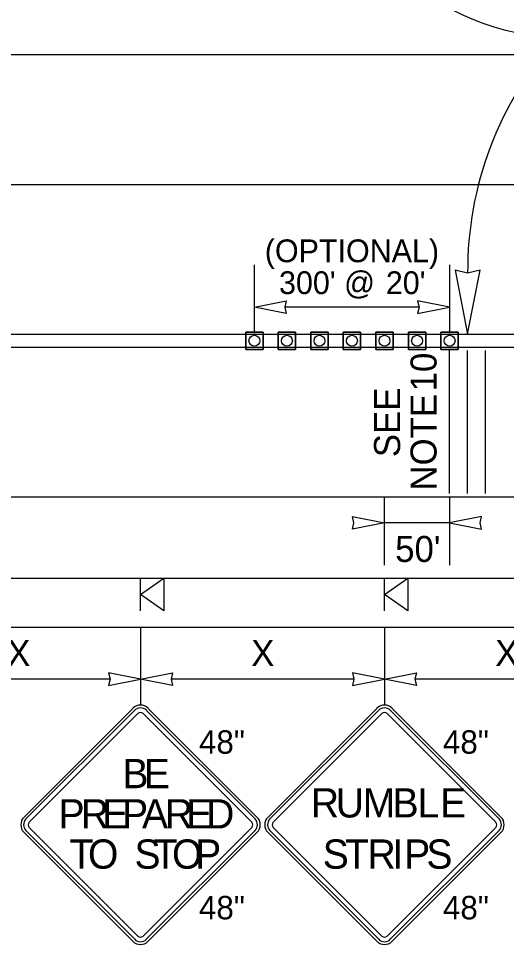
# Model space of a CAD drawing. Extents: x 99999.1 to 100095.7, y 99995 to 100010.7.
# Drawn here: x 100001.652 to 100003.152, y 100004.757 to 100007.603 of the extents above; entities that cross this region are included whole.
import ezdxf

# ---------------------------------------------------------------- set-up
doc = ezdxf.new("R2010")
doc.units = 0
for name, color, linetype in [('RD_ED_ShoulderPavedEdge', 7, 'Continuous'), ('RD_MK_LineDblYellowCenter', 7, 'Continuous'), ('RD_MK_LineEdgeWhite', 7, 'Continuous'), ('TR_SN_ConstructionSigns', 7, 'Continuous'), ('TR_WZ_PortableSignMountBlk-Org', 7, 'Continuous'), ('TR_WZ_TrafficCone', 7, 'Continuous'), ('TR_WZ_WorkZoneDetails', 7, 'Continuous'), ('TR_WZ_WorkZoneTextCurrent', 7, 'Continuous')]:
    doc.layers.add(name, color=color, linetype=linetype)

msp = doc.modelspace()

# ---------------------------------------------------------------- linework, layer by layer
at = {"layer": 'RD_ED_ShoulderPavedEdge'}
for p, q in [((100000.1076, 100007.4923), (100015.6424, 100007.4923)), ((100000.1076, 100005.7323), (100015.6424, 100005.7323))]:
    msp.add_line(p, q, dxfattribs=at)
at = {"layer": 'RD_MK_LineDblYellowCenter'}
for p, q in [((100000.1282, 100006.6323), (100003.4767, 100006.6323)), ((100000.0869, 100006.5923), (100003.4767, 100006.5923))]:
    msp.add_line(p, q, dxfattribs=at)
at = {"layer": 'RD_MK_LineEdgeWhite'}
for p, q in [((100000.1076, 100007.0923), (100015.6424, 100007.0923)), ((100000.1076, 100006.1323), (100015.6424, 100006.1323))]:
    msp.add_line(p, q, dxfattribs=at)
at = {"layer": 'TR_SN_ConstructionSigns'}
for p, q in [((100002.0028, 100005.4824), (100001.6687, 100005.1483)), ((100002.0088, 100005.4765), (100001.6746, 100005.1424)), ((100002.3787, 100005.1424), (100002.0445, 100005.4765)), ((100002.3846, 100005.1483), (100002.0505, 100005.4824)), ((100002.7528, 100005.4824), (100002.4187, 100005.1483)), ((100002.7588, 100005.4765), (100002.4246, 100005.1424)), ((100003.1287, 100005.1424), (100002.7945, 100005.4765)), ((100003.1346, 100005.1483), (100002.8005, 100005.4824)), ((100001.6846, 100005.1324), (100002.0187, 100005.4665)), ((100002.0346, 100005.4665), (100002.3687, 100005.1324)), ((100002.4346, 100005.1324), (100002.7687, 100005.4665)), ((100002.7846, 100005.4665), (100003.1187, 100005.1324)), ((100001.6746, 100005.1066), (100002.0088, 100004.7725)), ((100002.0187, 100004.7824), (100001.6846, 100005.1165)), ((100002.3687, 100005.1165), (100002.0346, 100004.7824)), ((100002.0445, 100004.7725), (100002.3787, 100005.1066)), ((100002.4246, 100005.1066), (100002.7588, 100004.7725)), ((100002.7687, 100004.7824), (100002.4346, 100005.1165)), ((100003.1187, 100005.1165), (100002.7846, 100004.7824)), ((100002.7945, 100004.7725), (100003.1287, 100005.1066)), ((100001.6687, 100005.1006), (100002.0028, 100004.7665)), ((100002.0505, 100004.7665), (100002.3846, 100005.1006)), ((100002.4187, 100005.1006), (100002.7528, 100004.7665)), ((100002.8005, 100004.7665), (100003.1346, 100005.1006))]:
    msp.add_line(p, q, dxfattribs=at)
for centre, radius, start, end in [((100002.0267, 100005.4586), 0.0338, 45, 135), ((100002.0267, 100005.4586), 0.0253, 45, 135), ((100002.7767, 100005.4586), 0.0338, 45, 135), ((100002.7767, 100005.4586), 0.0253, 45, 135), ((100002.0267, 100005.4586), 0.0113, 45, 135), ((100002.7767, 100005.4586), 0.0113, 45, 135), ((100001.6925, 100005.1245), 0.0338, 135, 225), ((100001.6925, 100005.1245), 0.0253, 135, 225), ((100001.6925, 100005.1245), 0.0113, 135, 225), ((100002.3608, 100005.1245), 0.0113, 315, 45), ((100002.3608, 100005.1245), 0.0253, 315, 45), ((100002.3608, 100005.1245), 0.0338, 315, 45), ((100002.4425, 100005.1245), 0.0338, 135, 225), ((100002.4425, 100005.1245), 0.0253, 135, 225), ((100002.4425, 100005.1245), 0.0113, 135, 225), ((100003.1108, 100005.1245), 0.0113, 315, 45), ((100003.1108, 100005.1245), 0.0253, 315, 45), ((100003.1108, 100005.1245), 0.0338, 315, 45), ((100002.0267, 100004.7904), 0.0338, 225, 315), ((100002.0267, 100004.7904), 0.0253, 225, 315), ((100002.0267, 100004.7904), 0.0113, 225, 315), ((100002.7767, 100004.7904), 0.0338, 225, 315), ((100002.7767, 100004.7904), 0.0253, 225, 315), ((100002.7767, 100004.7904), 0.0113, 225, 315)]:
    msp.add_arc(centre, radius, start, end, dxfattribs=at)
at = {"layer": 'TR_WZ_PortableSignMountBlk-Org'}
for p, q in [((100002.0267, 100005.7824), (100002.0267, 100005.8824)), ((100002.7767, 100005.7824), (100002.7767, 100005.8824))]:
    msp.add_line(p, q, dxfattribs=at)
for points in [[(100002.0267, 100005.8323), (100002.0985, 100005.8824), (100002.0985, 100005.7824)], [(100002.7767, 100005.8323), (100002.8485, 100005.8824), (100002.8485, 100005.7824)]]:
    msp.add_lwpolyline(points, close=True, dxfattribs=at)
at = {"layer": 'TR_WZ_TrafficCone'}
for points in [[(100002.4033, 100006.639), (100002.35, 100006.639), (100002.35, 100006.5857), (100002.4033, 100006.5857), (100002.4033, 100006.639)], [(100002.4033, 100006.5857), (100002.35, 100006.5857), (100002.35, 100006.639), (100002.4033, 100006.639), (100002.4033, 100006.5857)], [(100002.5033, 100006.639), (100002.45, 100006.639), (100002.45, 100006.5857), (100002.5033, 100006.5857), (100002.5033, 100006.639)], [(100002.5033, 100006.5857), (100002.45, 100006.5857), (100002.45, 100006.639), (100002.5033, 100006.639), (100002.5033, 100006.5857)], [(100002.6033, 100006.639), (100002.55, 100006.639), (100002.55, 100006.5857), (100002.6033, 100006.5857), (100002.6033, 100006.639)], [(100002.6033, 100006.5857), (100002.55, 100006.5857), (100002.55, 100006.639), (100002.6033, 100006.639), (100002.6033, 100006.5857)], [(100002.7033, 100006.639), (100002.65, 100006.639), (100002.65, 100006.5857), (100002.7033, 100006.5857), (100002.7033, 100006.639)], [(100002.7033, 100006.5857), (100002.65, 100006.5857), (100002.65, 100006.639), (100002.7033, 100006.639), (100002.7033, 100006.5857)], [(100002.8033, 100006.639), (100002.75, 100006.639), (100002.75, 100006.5857), (100002.8033, 100006.5857), (100002.8033, 100006.639)], [(100002.8033, 100006.5857), (100002.75, 100006.5857), (100002.75, 100006.639), (100002.8033, 100006.639), (100002.8033, 100006.5857)], [(100002.9033, 100006.639), (100002.85, 100006.639), (100002.85, 100006.5857), (100002.9033, 100006.5857), (100002.9033, 100006.639)], [(100002.9033, 100006.5857), (100002.85, 100006.5857), (100002.85, 100006.639), (100002.9033, 100006.639), (100002.9033, 100006.5857)], [(100003.0033, 100006.639), (100002.95, 100006.639), (100002.95, 100006.5857), (100003.0033, 100006.5857), (100003.0033, 100006.639)], [(100003.0033, 100006.5857), (100002.95, 100006.5857), (100002.95, 100006.639), (100003.0033, 100006.639), (100003.0033, 100006.5857)]]:
    msp.add_lwpolyline(points, dxfattribs=at)
for centre in [(100002.3767, 100006.6123), (100002.4767, 100006.6123), (100002.5767, 100006.6123), (100002.6767, 100006.6123), (100002.7767, 100006.6123), (100002.8767, 100006.6123), (100002.9767, 100006.6123)]:
    msp.add_circle(centre, 0.0167, dxfattribs=at)
at = {"layer": 'TR_WZ_WorkZoneDetails'}
for p, q in [((100002.3767, 100006.6357), (100002.3767, 100006.8457)), ((100002.9767, 100006.8457), (100002.9767, 100006.6357)), ((100002.8829, 100006.7157), (100002.4704, 100006.7157)), ((100002.9767, 100006.1423), (100002.9767, 100006.5823)), ((100003.0323, 100006.1423), (100003.0323, 100006.5823)), ((100003.0872, 100006.1423), (100003.0872, 100006.5823)), ((100002.7767, 100005.9223), (100002.7767, 100006.1323)), ((100002.9767, 100006.1323), (100002.9767, 100005.9223)), ((100002.9767, 100006.0523), (100002.7767, 100006.0523)), ((100000.5267, 100005.8824), (100003.5267, 100005.8824)), ((100002.0267, 100005.7323), (100002.0267, 100005.4923)), ((100002.7767, 100005.7323), (100002.7767, 100005.4923)), ((100001.9329, 100005.5723), (100001.3704, 100005.5723)), ((100002.6829, 100005.5723), (100002.1204, 100005.5723)), ((100003.4329, 100005.5723), (100002.8704, 100005.5723))]:
    msp.add_line(p, q, dxfattribs=at)
for points in [[(100003.0323, 100006.6323), (100003.0708, 100006.8289), (100003.0323, 100006.8198), (100002.9937, 100006.8289)], [(100002.3767, 100006.7157), (100002.4749, 100006.7349), (100002.4704, 100006.7157), (100002.4749, 100006.6964)], [(100002.9767, 100006.7157), (100002.8784, 100006.7349), (100002.8829, 100006.7157), (100002.8784, 100006.6964)], [(100002.7767, 100006.0523), (100002.6784, 100006.0331), (100002.6829, 100006.0523), (100002.6784, 100006.0716)], [(100002.9767, 100006.0523), (100003.0749, 100006.0331), (100003.0704, 100006.0523), (100003.0749, 100006.0716)], [(100002.0267, 100005.5723), (100001.9284, 100005.5916), (100001.9329, 100005.5723), (100001.9284, 100005.5531)], [(100002.0267, 100005.5723), (100002.1249, 100005.5916), (100002.1204, 100005.5723), (100002.1249, 100005.5531)], [(100002.7767, 100005.5723), (100002.6784, 100005.5916), (100002.6829, 100005.5723), (100002.6784, 100005.5531)], [(100002.7767, 100005.5723), (100002.8749, 100005.5916), (100002.8704, 100005.5723), (100002.8749, 100005.5531)]]:
    msp.add_lwpolyline(points, close=True, dxfattribs=at)
msp.add_circle((100003.3346, 100008.2843), 0.742, dxfattribs=at)
msp.add_arc((100004.1081, 100006.8268), 1.0759, 138.2705, 180.3733, dxfattribs=at)

# ---------------------------------------------------------------- texts
at = {"layer": 'TR_SN_ConstructionSigns'}
for p in [(100002.2064, 100005.343), (100002.9564, 100005.343), (100002.2064, 100004.8339), (100002.9564, 100004.8339)]:
    msp.add_text('48"', height=0.072, rotation=360, dxfattribs=at).set_placement(p)
for s, p in [('B', (100001.9709, 100005.237)), ('E', (100002.0366, 100005.237)), ('R', (100002.5503, 100005.147)), ('U', (100002.6268, 100005.147)), ('M', (100002.7096, 100005.147)), ('B', (100002.8014, 100005.147)), ('L', (100002.8779, 100005.147)), ('E', (100002.9472, 100005.147)), ('P', (100001.7747, 100005.1132)), ('R', (100001.8431, 100005.1132)), ('E', (100001.9088, 100005.1132)), ('P', (100001.97, 100005.1132)), ('A', (100002.0312, 100005.1132)), ('R', (100002.1014, 100005.1132)), ('E', (100002.1671, 100005.1132)), ('D', (100002.2283, 100005.1132)), ('T', (100001.8084, 100004.9895)), ('O', (100001.8651, 100004.9895)), ('S', (100002.0082, 100004.9895)), ('T', (100002.0667, 100004.9895)), ('O', (100002.1234, 100004.9895)), ('P', (100002.1945, 100004.9895)), ('S', (100002.5868, 100004.9895)), ('T', (100002.6552, 100004.9895)), ('R', (100002.7245, 100004.9895)), ('I', (100002.801, 100004.9895)), ('P', (100002.837, 100004.9895)), ('S', (100002.9054, 100004.9895))]:
    msp.add_text(s, height=0.09, dxfattribs=at).set_placement(p)
at = {"layer": 'TR_WZ_WorkZoneDetails'}
for s, p in [('10', (100002.9367, 100006.4566)), ('SEE', (100002.8247, 100006.2544)), ('NOTE', (100002.9367, 100006.1518))]:
    msp.add_text(s, height=0.08, rotation=90, dxfattribs=at).set_placement(p)
at = {"layer": 'TR_WZ_WorkZoneTextCurrent'}
for s, height, p in [('(OPTIONAL)', 0.07, (100002.4087, 100006.8537)), ("300' @", 0.07, (100002.4524, 100006.7557)), ("20'", 0.07, (100002.7808, 100006.7557)), ("50'", 0.08, (100002.8094, 100005.9323))]:
    msp.add_text(s, height=height, dxfattribs=at).set_placement(p)
for p in [(100001.6169, 100005.6123), (100002.3669, 100005.6123), (100003.1169, 100005.6123)]:
    msp.add_text('X', height=0.08, rotation=360, dxfattribs=at).set_placement(p)

doc.saveas('drawing.dxf')
